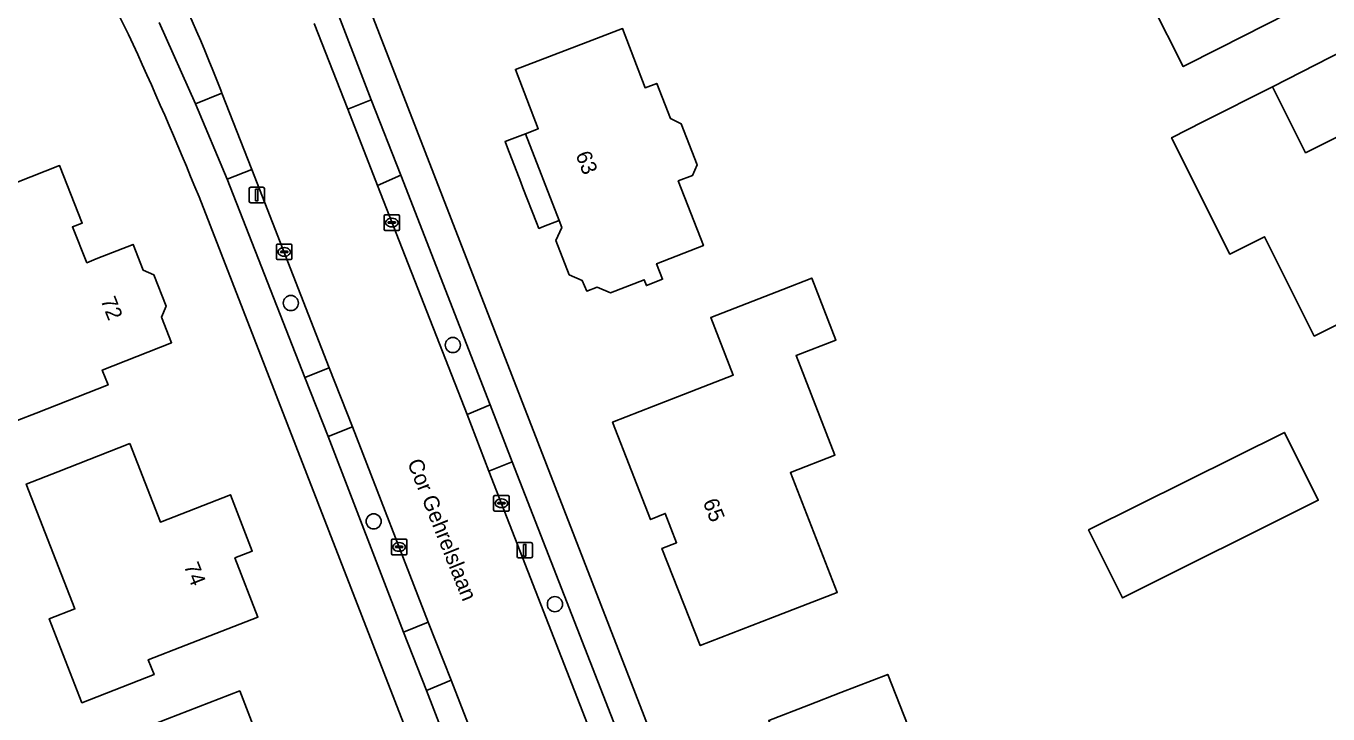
# Model space of a CAD drawing. Extents: x 157320 to 158835, y 386650 to 388491.
# Drawn here: x 158174.2 to 158258.3, y 387061.7 to 387106.1 of the extents above; entities that cross this region are included whole.
import ezdxf

# ---------------------------------------------------------------- set-up
doc = ezdxf.new("R2010")
doc.units = 0
for name, color, linetype in [('IMGEO_Boom', 7, 'Continuous'), ('IMGEO_Erf', 7, 'Continuous'), ('IMGEO_Groenvoorziening', 7, 'Continuous'), ('IMGEO_Kolk', 7, 'Continuous'), ('IMGEO_Lichtmast', 7, 'Continuous'), ('IMGEO_Openbare_ruimte_label', 7, 'Continuous'), ('IMGEO_Pand', 7, 'Continuous'), ('IMGEO_Pand_nummerreeks', 7, 'Continuous'), ('IMGEO_Pand_overbouw', 7, 'Continuous'), ('IMGEO_Rijbaan_lokaal_gesloten', 7, 'Continuous'), ('IMGEO_Voetpad_open', 7, 'Continuous')]:
    doc.layers.add(name, color=color, linetype=linetype)

msp = doc.modelspace()

# ---------------------------------------------------------------- linework, layer by layer
at = {"layer": 'IMGEO_Boom'}
for centre in [(158191.308, 387088.211), (158201.773, 387085.498), (158196.66, 387074.108), (158208.369, 387068.761)]:
    msp.add_circle(centre, 0.489, dxfattribs=at)
at = {"layer": 'IMGEO_Erf'}
for points in [[(158261.678, 387106.873), (158255.854, 387118.733), (158255.247, 387119.838), (158254.302, 387121.713), (158251.973, 387126.362), (158247.5, 387135.026), (158246.883, 387136.25), (158244.746, 387140.374), (158242.976, 387143.859), (158242.788, 387144.259), (158239.212, 387145.028), (158238.788, 387144.816), (158216.637, 387133.751), (158209.166, 387129.993), (158193.552, 387122.165), (158192.002, 387118.576), (158215.25, 387058.634)], [(158255.747, 387106.935), (158251.289, 387104.672), (158248.954, 387103.486), (158246.897, 387107.537)], [(158171.716, 387095.269), (158176.369, 387097.096), (158177.833, 387093.372), (158177.201, 387093.124), (158178.134, 387090.814), (158178.739, 387091.063), (158181.117, 387091.997), (158181.776, 387090.333), (158182.453, 387090.042), (158183.259, 387088), (158182.963, 387087.299), (158183.602, 387085.643), (158179.126, 387083.885), (158179.503, 387082.924), (158174.85, 387081.097), (158173.629, 387080.617)], [(158209.958, 387031.786), (158185.382, 387095.063)]]:
    msp.add_lwpolyline(points, dxfattribs=at)
for points in [[(158217.558, 387097.135), (158217.263, 387096.46), (158216.332, 387096.096), (158217.958, 387091.928), (158214.931, 387090.747), (158215.321, 387089.751), (158214.278, 387089.344), (158214.132, 387089.717), (158211.952, 387088.866), (158211.088, 387089.246), (158210.425, 387088.988), (158210.135, 387089.661), (158209.289, 387090.036), (158208.437, 387092.249), (158208.817, 387093.091), (158208.641, 387093.542), (158206.461, 387099.146), (158207.289, 387099.465), (158205.812, 387103.307), (158210.485, 387105.088), (158212.735, 387105.946), (158214.196, 387102.114), (158214.945, 387102.4), (158215.834, 387100.122), (158216.528, 387099.796)], [(158248.206, 387098.888), (158250.26, 387099.928), (158254.72, 387102.186), (158256.858, 387097.915), (158260.595, 387099.785), (158262.95, 387095.081), (158265.452, 387090.085), (158260.979, 387087.852), (158257.418, 387086.074), (158254.21, 387092.499), (158251.958, 387091.375)], [(158226.46, 387078.384), (158223.577, 387077.256), (158226.608, 387069.513), (158222.419, 387067.893), (158217.755, 387066.089), (158215.282, 387072.357), (158216.232, 387072.728), (158215.493, 387074.618), (158214.545, 387074.229), (158212.09, 387080.517), (158214.737, 387081.548), (158219.887, 387083.554), (158218.436, 387087.281), (158223.096, 387089.096), (158224.957, 387089.821), (158226.516, 387085.816), (158223.952, 387084.817)], [(158245.034, 387069.165), (158242.846, 387073.553), (158255.494, 387079.859), (158257.682, 387075.471)], [(158180.919, 387079.128), (158182.888, 387074.067), (158187.406, 387075.824), (158188.819, 387072.194), (158187.699, 387071.753), (158189.187, 387067.922), (158184.527, 387066.11), (158182.102, 387065.167), (158182.475, 387064.21), (158177.811, 387062.396), (158175.705, 387067.813), (158177.358, 387068.456), (158174.221, 387076.522), (158176.26, 387077.315)], [(158239.172, 387051.986), (158235.27, 387050.43), (158230.972, 387048.764), (158230.945, 387048.036), (158227.7, 387046.757), (158227.144, 387047.28), (158226.275, 387046.944), (158223.573, 387053.843), (158222.078, 387057.659), (158223.374, 387058.161), (158222.182, 387061.247), (158224.757, 387062.242), (158226.847, 387063.049), (158229.87, 387064.217), (158231.416, 387060.27), (158232.386, 387060.651), (158235.353, 387053.05), (158238.306, 387054.203)], [(158179.653, 387059.92), (158183.344, 387061.351), (158188.005, 387063.158), (158189.628, 387058.973), (158193.441, 387060.451), (158195.686, 387054.692), (158195.034, 387054.438), (158195.688, 387052.761), (158196.34, 387053.015), (158197.61, 387049.753), (158192.949, 387047.946), (158188.774, 387046.327), (158185.962, 387053.582), (158182.613, 387052.284)]]:
    msp.add_lwpolyline(points, close=True, dxfattribs=at)
for centre, radius, start, end in [((158110.195, 387071.005), 78.635, 26.07334, 37.27421), ((157932.631, 386991.722), 273.061, 22.23789, 24.64032)]:
    msp.add_arc(centre, radius, start, end, dxfattribs=at)
at = {"layer": 'IMGEO_Groenvoorziening'}
for points in [[(158192.819, 387106.264), (158194.993, 387100.728), (158196.498, 387101.337), (158188.513, 387122.106)], [(158182.813, 387106.342), (158185.153, 387101.086), (158186.845, 387101.76), (158186.779, 387101.964)]]:
    msp.add_lwpolyline(points, dxfattribs=at)
for points in [[(158188.788, 387096.838), (158187.204, 387096.22), (158192.221, 387083.393), (158193.794, 387084.016)], [(158204.177, 387081.627), (158198.408, 387096.474), (158196.899, 387095.81), (158202.689, 387081.018)], [(158200.191, 387067.589), (158195.292, 387080.209), (158193.727, 387079.581), (158198.594, 387066.956)], [(158205.614, 387077.958), (158204.1, 387077.351), (158211.307, 387058.859), (158212.819, 387059.448)], [(158201.673, 387063.843), (158200.068, 387063.193), (158205.771, 387048.391), (158207.412, 387049.027)]]:
    msp.add_lwpolyline(points, close=True, dxfattribs=at)
msp.add_arc((158107.649, 387071.85), 84.666, 20.83474, 28.28255, dxfattribs=at)
at = {"layer": 'IMGEO_Kolk'}
for p, q in [((158197.406, 387093.908), (158198.258, 387093.908)), ((158197.331, 387092.982), (158197.331, 387093.834)), ((158197.59, 387093.402), (158197.59, 387093.414)), ((158198.028, 387093.365), (158197.63, 387093.365)), ((158197.633, 387093.451), (158198.031, 387093.451)), ((158197.842, 387093.128), (158197.817, 387093.128)), ((158197.819, 387093.688), (158197.844, 387093.688)), ((158198.074, 387093.414), (158198.074, 387093.402)), ((158198.332, 387093.834), (158198.332, 387092.982)), ((158198.258, 387092.908), (158197.406, 387092.908)), ((158190.38, 387091.089), (158190.38, 387091.941)), ((158190.455, 387092.015), (158191.307, 387092.015)), ((158190.639, 387091.509), (158190.639, 387091.521)), ((158191.077, 387091.472), (158190.679, 387091.472)), ((158190.682, 387091.558), (158191.08, 387091.558)), ((158190.868, 387091.795), (158190.893, 387091.795)), ((158191.123, 387091.521), (158191.123, 387091.509)), ((158191.381, 387091.941), (158191.381, 387091.089)), ((158191.307, 387091.015), (158190.455, 387091.015)), ((158190.891, 387091.235), (158190.866, 387091.235)), ((158204.411, 387074.852), (158204.411, 387075.704)), ((158204.486, 387075.778), (158205.338, 387075.778)), ((158204.899, 387075.558), (158204.924, 387075.558)), ((158205.412, 387075.704), (158205.412, 387074.852)), ((158205.338, 387074.778), (158204.486, 387074.778)), ((158204.67, 387075.272), (158204.67, 387075.284)), ((158205.108, 387075.235), (158204.71, 387075.235)), ((158204.713, 387075.321), (158205.111, 387075.321)), ((158204.922, 387074.998), (158204.897, 387074.998)), ((158205.154, 387075.284), (158205.154, 387075.272)), ((158197.803, 387072.028), (158197.803, 387072.88)), ((158197.878, 387072.954), (158198.73, 387072.954)), ((158198.804, 387072.88), (158198.804, 387072.028)), ((158198.062, 387072.448), (158198.062, 387072.46)), ((158198.5, 387072.411), (158198.102, 387072.411)), ((158198.105, 387072.497), (158198.503, 387072.497)), ((158198.314, 387072.174), (158198.289, 387072.174)), ((158198.291, 387072.734), (158198.316, 387072.734)), ((158198.546, 387072.46), (158198.546, 387072.448)), ((158198.73, 387071.954), (158197.878, 387071.954))]:
    msp.add_line(p, q, dxfattribs=at)
for points in [[(158197.406, 387093.908), (158198.258, 387093.908)], [(158197.331, 387092.982), (158197.331, 387093.834)], [(158198.332, 387093.834), (158198.332, 387092.982)], [(158198.258, 387092.908), (158197.406, 387092.908)], [(158190.38, 387091.089), (158190.38, 387091.941)], [(158190.455, 387092.015), (158191.307, 387092.015)], [(158191.381, 387091.941), (158191.381, 387091.089)], [(158191.307, 387091.015), (158190.455, 387091.015)], [(158204.411, 387074.852), (158204.411, 387075.704)], [(158204.486, 387075.778), (158205.338, 387075.778)], [(158205.412, 387075.704), (158205.412, 387074.852)], [(158205.338, 387074.778), (158204.486, 387074.778)], [(158197.803, 387072.028), (158197.803, 387072.88)], [(158197.878, 387072.954), (158198.73, 387072.954)], [(158198.804, 387072.88), (158198.804, 387072.028)], [(158198.73, 387071.954), (158197.878, 387071.954)]]:
    msp.add_lwpolyline(points, dxfattribs=at)
for centre, radius, start, end in [((158197.408, 387093.832), 0.0765, 91.55205, 178.44795), ((158197.408, 387093.832), 0.0765, 91.55205, 178.44795), ((158198.256, 387093.832), 0.0765, 1.55205, 88.44795), ((158198.256, 387093.832), 0.0765, 1.55205, 88.44795), ((158197.63, 387093.411), 0.0403, 85.87752, 175.75265), ((158197.627, 387093.401), 0.0366, 178.93798, 274.71019), ((158198.031, 387093.408), 0.043, 264.86636, 352.45326), ((158198.035, 387093.413), 0.0386, 1.73085, 96.63898), ((158197.408, 387092.984), 0.0765, 181.55205, 268.44795), ((158197.408, 387092.984), 0.0765, 181.55205, 268.44795), ((158198.256, 387092.984), 0.0765, 271.55205, 358.44795), ((158198.256, 387092.984), 0.0765, 271.55205, 358.44795), ((158190.457, 387091.939), 0.0765, 91.55205, 178.44795), ((158190.457, 387091.939), 0.0765, 91.55205, 178.44795), ((158190.679, 387091.518), 0.0403, 85.87752, 175.75265), ((158190.676, 387091.508), 0.0366, 178.93798, 274.71019), ((158191.08, 387091.515), 0.043, 264.86636, 352.45326), ((158191.084, 387091.52), 0.0386, 1.73085, 96.63898), ((158191.305, 387091.939), 0.0765, 1.55205, 88.44795), ((158191.305, 387091.939), 0.0765, 1.55205, 88.44795), ((158190.457, 387091.091), 0.0765, 181.55205, 268.44795), ((158190.457, 387091.091), 0.0765, 181.55205, 268.44795), ((158191.305, 387091.091), 0.0765, 271.55205, 358.44795), ((158191.305, 387091.091), 0.0765, 271.55205, 358.44795), ((158204.488, 387075.702), 0.0765, 91.55205, 178.44795), ((158204.488, 387075.702), 0.0765, 91.55205, 178.44795), ((158205.336, 387075.702), 0.0765, 1.55205, 88.44795), ((158205.336, 387075.702), 0.0765, 1.55205, 88.44795), ((158204.488, 387074.854), 0.0765, 181.55205, 268.44795), ((158204.488, 387074.854), 0.0765, 181.55205, 268.44795), ((158204.71, 387075.281), 0.0403, 85.87752, 175.75265), ((158204.707, 387075.271), 0.0366, 178.93798, 274.71019), ((158205.111, 387075.278), 0.043, 264.86636, 352.45326), ((158205.115, 387075.283), 0.0386, 1.73085, 96.63898), ((158205.336, 387074.854), 0.0765, 271.55205, 358.44795), ((158205.336, 387074.854), 0.0765, 271.55205, 358.44795), ((158197.88, 387072.878), 0.0765, 91.55205, 178.44795), ((158197.88, 387072.878), 0.0765, 91.55205, 178.44795), ((158198.728, 387072.878), 0.0765, 1.55205, 88.44795), ((158198.728, 387072.878), 0.0765, 1.55205, 88.44795), ((158197.88, 387072.03), 0.0765, 181.55205, 268.44795), ((158197.88, 387072.03), 0.0765, 181.55205, 268.44795), ((158198.102, 387072.457), 0.0403, 85.87752, 175.75265), ((158198.099, 387072.447), 0.0366, 178.93798, 274.71019), ((158198.503, 387072.454), 0.043, 264.86636, 352.45326), ((158198.507, 387072.459), 0.0386, 1.73085, 96.63898), ((158198.728, 387072.03), 0.0765, 271.55205, 358.44795), ((158198.728, 387072.03), 0.0765, 271.55205, 358.44795)]:
    msp.add_arc(centre, radius, start, end, dxfattribs=at)
for centre, major_axis, ratio, start_param, end_param in [((158197.818, 387093.408), (-0.387, 0.002), 0.722429, 4.712389, 7.853982), ((158197.843, 387093.408), (-0.39, 0.002), 0.717154, 1.570796, 4.712389), ((158190.867, 387091.515), (-0.387, 0.002), 0.722429, 4.712389, 7.853982), ((158190.892, 387091.515), (-0.39, 0.002), 0.717154, 1.570796, 4.712389), ((158204.898, 387075.278), (-0.387, 0.002), 0.722429, 4.712389, 7.853982), ((158204.923, 387075.278), (-0.39, 0.002), 0.717154, 1.570796, 4.712389), ((158198.29, 387072.454), (-0.387, 0.002), 0.722429, 4.712389, 7.853982), ((158198.315, 387072.454), (-0.39, 0.002), 0.717154, 1.570796, 4.712389)]:
    msp.add_ellipse(centre, major_axis=major_axis, ratio=ratio, start_param=start_param, end_param=end_param, dxfattribs=at)
at = {"layer": 'IMGEO_Lichtmast'}
for p, q in [((158188.616, 387094.79), (158188.616, 387095.59)), ((158188.616, 387095.59), (158188.616, 387094.79)), ((158188.716, 387095.69), (158189.506, 387095.69)), ((158189.506, 387095.69), (158188.716, 387095.69)), ((158189.606, 387095.59), (158189.606, 387094.79)), ((158189.606, 387094.79), (158189.606, 387095.59)), ((158189.506, 387094.69), (158188.716, 387094.69)), ((158188.716, 387094.69), (158189.506, 387094.69)), ((158205.923, 387071.846), (158205.923, 387072.646)), ((158205.923, 387072.646), (158205.923, 387071.846)), ((158206.023, 387072.746), (158206.813, 387072.746)), ((158206.813, 387072.746), (158206.023, 387072.746)), ((158206.913, 387072.646), (158206.913, 387071.846)), ((158206.913, 387071.846), (158206.913, 387072.646)), ((158206.813, 387071.746), (158206.023, 387071.746)), ((158206.023, 387071.746), (158206.813, 387071.746))]:
    msp.add_line(p, q, dxfattribs=at)
for points in [[(158189.036, 387095.565), (158189.186, 387095.565), (158189.186, 387094.815), (158189.036, 387094.815), (158189.036, 387095.565)], [(158206.343, 387072.621), (158206.493, 387072.621), (158206.493, 387071.871), (158206.343, 387071.871), (158206.343, 387072.621)]]:
    msp.add_lwpolyline(points, dxfattribs=at)
for centre, start, end in [((158188.716, 387095.59), 90, 180), ((158188.716, 387095.59), 90, 180), ((158189.506, 387095.59), 0, 90), ((158189.506, 387095.59), 360, 90), ((158188.716, 387094.79), 180, 270), ((158188.716, 387094.79), 180, 270), ((158189.506, 387094.79), 270, 0), ((158189.506, 387094.79), 270, 0), ((158206.023, 387072.646), 90, 180), ((158206.023, 387072.646), 90, 180), ((158206.813, 387072.646), 0, 90), ((158206.813, 387072.646), 360, 90), ((158206.023, 387071.846), 180, 270), ((158206.023, 387071.846), 180, 270), ((158206.813, 387071.846), 270, 0), ((158206.813, 387071.846), 270, 0)]:
    msp.add_arc(centre, 0.1, start, end, dxfattribs=at)
at = {"layer": 'IMGEO_Pand'}
for points in [[(158246.897, 387107.537), (158248.954, 387103.486), (158251.289, 387104.672), (158255.747, 387106.935)], [(158173.629, 387080.617), (158174.85, 387081.097), (158179.503, 387082.924), (158179.126, 387083.885), (158183.602, 387085.643), (158182.963, 387087.299), (158183.259, 387088), (158182.453, 387090.042), (158181.776, 387090.333), (158181.117, 387091.997), (158178.739, 387091.063), (158178.134, 387090.814), (158177.201, 387093.124), (158177.833, 387093.372), (158176.369, 387097.096), (158171.716, 387095.269)]]:
    msp.add_lwpolyline(points, dxfattribs=at)
for points in [[(158216.528, 387099.796), (158215.834, 387100.122), (158214.945, 387102.4), (158214.196, 387102.114), (158212.735, 387105.946), (158210.485, 387105.088), (158205.812, 387103.307), (158207.289, 387099.465), (158206.461, 387099.146), (158208.641, 387093.542), (158208.817, 387093.091), (158208.437, 387092.249), (158209.289, 387090.036), (158210.135, 387089.661), (158210.425, 387088.988), (158211.088, 387089.246), (158211.952, 387088.866), (158214.132, 387089.717), (158214.278, 387089.344), (158215.321, 387089.751), (158214.931, 387090.747), (158217.958, 387091.928), (158216.332, 387096.096), (158217.263, 387096.46), (158217.558, 387097.135)], [(158254.72, 387102.186), (158250.26, 387099.928), (158248.206, 387098.888), (158251.958, 387091.375), (158254.21, 387092.499), (158257.418, 387086.074), (158260.979, 387087.852), (158265.452, 387090.085), (158262.95, 387095.081), (158260.595, 387099.785), (158256.858, 387097.915)], [(158218.436, 387087.281), (158219.887, 387083.554), (158214.737, 387081.548), (158212.09, 387080.517), (158214.545, 387074.229), (158215.493, 387074.618), (158216.232, 387072.728), (158215.282, 387072.357), (158217.755, 387066.089), (158222.419, 387067.893), (158226.608, 387069.513), (158223.577, 387077.256), (158226.46, 387078.384), (158223.952, 387084.817), (158226.516, 387085.816), (158224.957, 387089.821), (158223.096, 387089.096)], [(158242.846, 387073.553), (158245.034, 387069.165), (158257.682, 387075.471), (158255.494, 387079.859)], [(158180.919, 387079.128), (158176.26, 387077.315), (158174.221, 387076.522), (158177.358, 387068.456), (158175.705, 387067.813), (158177.811, 387062.396), (158182.475, 387064.21), (158182.102, 387065.167), (158184.527, 387066.11), (158189.187, 387067.922), (158187.699, 387071.753), (158188.819, 387072.194), (158187.406, 387075.824), (158182.888, 387074.067)], [(158224.757, 387062.242), (158222.182, 387061.247), (158223.374, 387058.161), (158222.078, 387057.659), (158223.573, 387053.843), (158226.275, 387046.944), (158227.144, 387047.28), (158227.7, 387046.757), (158230.945, 387048.036), (158230.972, 387048.764), (158235.27, 387050.43), (158239.172, 387051.986), (158238.306, 387054.203), (158235.353, 387053.05), (158232.386, 387060.651), (158231.416, 387060.27), (158229.87, 387064.217), (158226.847, 387063.049)], [(158195.686, 387054.692), (158193.441, 387060.451), (158189.628, 387058.973), (158188.005, 387063.158), (158183.344, 387061.351), (158179.653, 387059.92), (158182.613, 387052.284), (158185.962, 387053.582), (158188.774, 387046.327), (158192.949, 387047.946), (158197.61, 387049.753), (158196.34, 387053.015), (158195.688, 387052.761), (158195.034, 387054.438)]]:
    msp.add_lwpolyline(points, close=True, dxfattribs=at)
at = {"layer": 'IMGEO_Pand_overbouw'}
for points in [[(158254.72, 387102.186), (158256.858, 387097.915), (158260.595, 387099.785), (158262.95, 387095.081), (158263.642, 387095.418), (158263.933, 387095.559), (158263.727, 387095.975), (158261.78, 387099.887), (158261.588, 387100.272), (158259.637, 387104.194), (158259.445, 387104.578), (158258.473, 387104.086)], [(158208.641, 387093.542), (158206.461, 387099.146), (158205.44, 387098.749), (158205.15, 387098.636), (158205.303, 387098.244), (158206.17, 387096.022), (158206.303, 387095.644), (158207.186, 387093.417), (158207.333, 387093.033), (158207.623, 387093.146)]]:
    msp.add_lwpolyline(points, close=True, dxfattribs=at)
at = {"layer": 'IMGEO_Rijbaan_lokaal_gesloten'}
for points in [[(158211.307, 387058.859), (158204.1, 387077.351), (158202.689, 387081.018), (158196.899, 387095.81), (158194.993, 387100.728), (158192.819, 387106.264)], [(158186.779, 387101.964), (158186.845, 387101.76), (158188.788, 387096.838), (158193.794, 387084.016), (158195.292, 387080.209), (158200.191, 387067.589), (158201.673, 387063.843), (158207.412, 387049.027), (158209.565, 387043.566), (158213.249, 387034.182), (158219.519, 387018.157), (158219.507, 387018.022), (158226.211, 387020.702), (158221.295, 387033.291), (158218.932, 387039.336), (158213.536, 387053.162), (158211.307, 387058.859)]]:
    msp.add_lwpolyline(points, dxfattribs=at)
msp.add_arc((158107.649, 387071.85), 84.666, 20.83474, 28.28255, dxfattribs=at)
at = {"layer": 'IMGEO_Voetpad_open'}
for points in [[(158188.513, 387122.106), (158196.498, 387101.337), (158198.408, 387096.474), (158204.177, 387081.627), (158205.614, 387077.958), (158212.819, 387059.448), (158215.039, 387053.749), (158220.735, 387039.162), (158222.528, 387034.561), (158232.88, 387008.083), (158233.401, 387006.768)], [(158235.235, 387007.476), (158234.598, 387009.079), (158215.25, 387058.634), (158192.002, 387118.576)], [(158200.068, 387063.193), (158198.594, 387066.956), (158193.727, 387079.581), (158192.221, 387083.393), (158187.204, 387096.22), (158185.153, 387101.086), (158182.813, 387106.342)], [(158185.382, 387095.063), (158209.958, 387031.786)], [(158213.022, 387029.745), (158207.897, 387042.911), (158205.771, 387048.391), (158200.068, 387063.193)]]:
    msp.add_lwpolyline(points, dxfattribs=at)
for points in [[(158186.845, 387101.76), (158185.153, 387101.086), (158187.204, 387096.22), (158188.788, 387096.838)], [(158194.993, 387100.728), (158196.899, 387095.81), (158198.408, 387096.474), (158196.498, 387101.337)], [(158195.292, 387080.209), (158193.794, 387084.016), (158192.221, 387083.393), (158193.727, 387079.581)], [(158204.177, 387081.627), (158202.689, 387081.018), (158204.1, 387077.351), (158205.614, 387077.958)], [(158200.191, 387067.589), (158198.594, 387066.956), (158200.068, 387063.193), (158201.673, 387063.843)]]:
    msp.add_lwpolyline(points, close=True, dxfattribs=at)
for centre, radius, start, end in [((158110.195, 387071.005), 78.635, 26.07334, 37.27421), ((157932.631, 386991.722), 273.061, 22.23789, 24.64032)]:
    msp.add_arc(centre, radius, start, end, dxfattribs=at)

# ---------------------------------------------------------------- texts
at = {"layer": 'IMGEO_Openbare_ruimte_label'}
msp.add_text('Cor Gehrelslaan', height=1, rotation=291.84398, dxfattribs=at).set_placement((158198.814, 387077.913))
at = {"layer": 'IMGEO_Pand_nummerreeks'}
for s, rotation, p in [('63', 291.26225, (158209.688, 387097.802)), ('72', 291.35966, (158179.004, 387088.398)), ('65', 291.35576, (158217.909, 387075.36)), ('74', 291.22668, (158184.38, 387071.237))]:
    msp.add_text(s, height=1, rotation=rotation, dxfattribs=at).set_placement(p)

doc.saveas('drawing.dxf')
